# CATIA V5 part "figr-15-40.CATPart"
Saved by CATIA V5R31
Part number: Part1
Bounding box of the stored display mesh (mm): x -55.204 to 69.266, y -33.79 to 44.107, z 0 to 118.408
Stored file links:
  D:\PROJECTS\Project 2021\US EDITION\CATIA V5 6R 2021\Resources\Part Files\c15_catia_v5_6r2021_prt\figr-15-40.CATPart
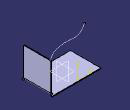
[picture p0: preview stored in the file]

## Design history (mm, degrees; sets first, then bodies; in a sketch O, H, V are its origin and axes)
SheetMetalParameters1: Thickness 2, BendRadius 4, KFactor 0.400515 {= log(min(100,max(20*SheetMetalParameters1.BendRadius,SheetMetalParameters1.Thickness)/SheetMetalParameters1.Thickness))/log(100)/2}, ReliefRadialLength 1, ReliefAxialLength 2, MinimumBendRadius 0
Body1 (main body)
  Sketch1 on xy-plane, origin (0, 0, 0), H (1, 0, 0), V (0, 1, 0)
    line L1 (-55.2037, 44.1067) -> (69.266, 44.1067)
    line L2 (69.266, 44.1067) -> (69.266, -33.7896)
    line L3 (69.266, -33.7896) -> (-55.2037, -33.7896)
    line L4 (-55.2037, -33.7896) -> (-55.2037, 44.1067)
    horizontal: L1 H, L3 H
    vertical: L2 V, L4 V
  Wall1: Thickness 2, Profile Sketch1, OffsetValue 0
  d_NewWallOnEdge1: NewWallOnEdge_Length 77.8964, NewWallOnEdge_HeightLimitOffset 0, NewWallOnEdge_WidthOffset1 -4, NewWallOnEdge_WidthOffset2 -4, NewWallOnEdge_Angle 90, NewWallOnEdge_BendRadiusValue 4 {= SheetMetalParameters1.BendRadius}, NewWallOnEdge_BendTable SheetMetalParameters1, NewWallOnEdge_Edge edge [face of Wall1 | face of Wall1], NewWallOnEdge_GapValue 0, KFacteur 0.400515 {= log(min(100,max(20*d_NewWallOnEdge1.Radius,SheetMetalParameters1.Thickness)/SheetMetalParameters1.Thickness))/log(100)/2}
  Sketch2 on face of d_NewWallOnEdge1, origin (0, 40.1067, 0), H (-1, 0, 0), V (0, 0, 1)
    spline S1 through (-69.266, 77.8964) (-67.9767, 84.9607) (-48.7678, 98.5965) (6.1586, 103.3856) (17.3621, 118.4076)
    reference projected line E1 (-69.266, 6) -> (-69.266, 77.8964) from edge [face of d_NewWallOnEdge1 | face of d_NewWallOnEdge1]
    reference projected line E2 (-69.266, 6) -> (-69.266, 77.8964) from edge [face of d_NewWallOnEdge1 | face of d_NewWallOnEdge1]
    reference projected point E3 (-69.266, 77.8964) from vertex [face of d_NewWallOnEdge1 | face of d_NewWallOnEdge1 | face of d_NewWallOnEdge1]
    point P1 (-69.266, 77.8964)
    coincidence: P1 E1, P1 E3
    tangency: S1 E2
